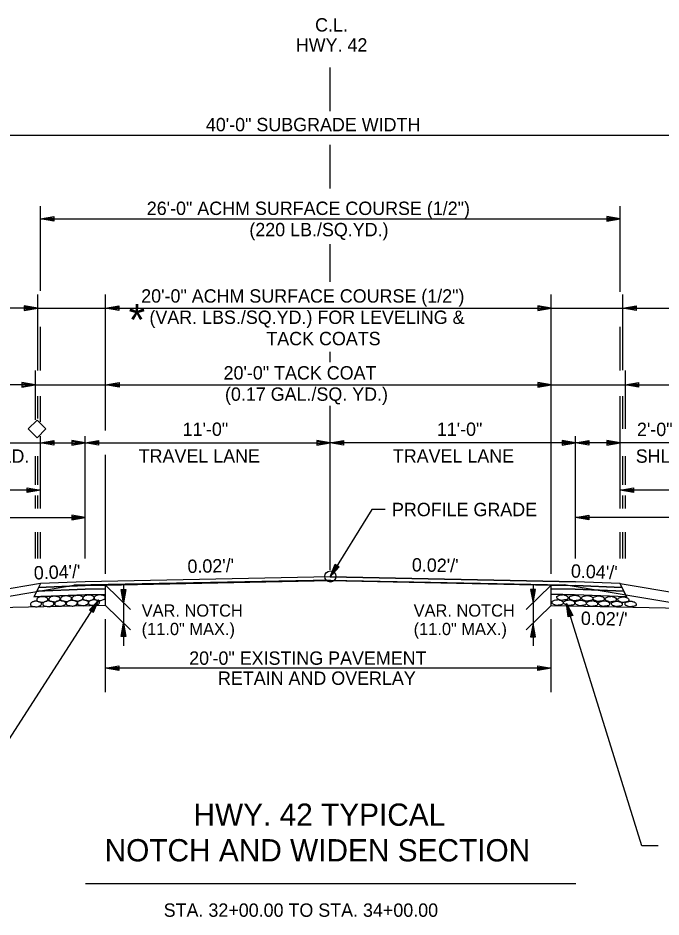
# Model space of a CAD drawing. Extents: x 1461570 to 1461697, y 1686711 to 1686957.
# Drawn here: x 1461592.73 to 1461621.58, y 1686771.55 to 1686811.92 of the extents above; entities that cross this region are included whole.
import ezdxf

# ---------------------------------------------------------------- set-up
doc = ezdxf.new("R2010")
doc.units = 0
for name, color, linetype in [('1', 7, 'Continuous'), ('10', 7, 'Continuous'), ('19', 7, 'Continuous'), ('20', 7, 'Continuous'), ('3', 7, 'Continuous'), ('42', 7, 'Continuous'), ('Default', 7, 'Continuous'), ('Level 1', 7, 'Continuous'), ('Level 9', 7, 'Continuous'), ('R_Draft', 7, 'Continuous'), ('R_Prop Surface', 7, 'Continuous')]:
    doc.layers.add(name, color=color, linetype=linetype)

# ---------------------------------------------------------------- blocks, each defined once
blk = doc.blocks.new('ROCKS')
at = {"layer": '1'}
blk.add_spline([(0.013, 0.06), (0.053, 0.053), (0.107, 0.033), (0.133, 0.013), (0.133, -0.007), (0.12, -0.033), (0.107, -0.04), (0.073, -0.053), (0.033, -0.067), (0.013, -0.067), (-0.02, -0.06), (-0.06, -0.053), (-0.087, -0.047), (-0.113, -0.02), (-0.113, -0.007), (-0.107, 0.02), (-0.087, 0.033), (-0.067, 0.047), (-0.033, 0.053), (-0.02, 0.06), (0.013, 0.06)], degree=3, dxfattribs=at)

msp = doc.modelspace()

# ---------------------------------------------------------------- linework, layer by layer
at = {"layer": '10'}
msp.add_lwpolyline([(1461593.585, 1686793.864), (1461593.983, 1686793.466), (1461593.585, 1686793.068), (1461593.187, 1686793.466)], close=True, dxfattribs=at)
at = {"layer": '19'}
for p, q in [((1461593.138, 1686790.605), (1461593.138, 1686790.815)), ((1461593.138, 1686790.815), (1461593.738, 1686790.71)), ((1461593.138, 1686790.76), (1461593.578, 1686790.725)), ((1461593.738, 1686790.71), (1461593.138, 1686790.605)), ((1461593.578, 1686790.695), (1461593.138, 1686790.655)), ((1461619.738, 1686790.71), (1461620.338, 1686790.815)), ((1461620.338, 1686790.605), (1461619.738, 1686790.71)), ((1461619.898, 1686790.725), (1461620.338, 1686790.76)), ((1461620.338, 1686790.655), (1461619.898, 1686790.695)), ((1461620.338, 1686790.815), (1461620.338, 1686790.605)), ((1461606.738, 1686786.821), (1461606.961, 1686787.387)), ((1461607.139, 1686787.278), (1461606.738, 1686786.821)), ((1461606.812, 1686786.962), (1461607.004, 1686787.355)), ((1461607.098, 1686787.299), (1461606.834, 1686786.95)), ((1461606.961, 1686787.387), (1461607.139, 1686787.278)), ((1461593.738, 1686786.521), (1461581.738, 1686784.521)), ((1461593.738, 1686786.521), (1461593.654, 1686786.351)), ((1461593.738, 1686786.521), (1461593.654, 1686786.351)), ((1461606.738, 1686786.821), (1461595.738, 1686786.601)), ((1461606.741, 1686786.654), (1461595.743, 1686786.434)), ((1461596.654, 1686785.535), (1461596.654, 1686786.452)), ((1461596.654, 1686786.452), (1461596.654, 1686786.452)), ((1461596.654, 1686786.286), (1461596.654, 1686786.452)), ((1461596.654, 1686786.452), (1461596.654, 1686786.452)), ((1461606.734, 1686786.654), (1461617.733, 1686786.434)), ((1461606.738, 1686786.821), (1461617.738, 1686786.601)), ((1461617.738, 1686786.601), (1461606.738, 1686786.821)), ((1461606.738, 1686786.654), (1461616.654, 1686786.456)), ((1461616.654, 1686785.539), (1461616.654, 1686786.456)), ((1461616.654, 1686786.289), (1461616.654, 1686786.456)), ((1461616.654, 1686786.456), (1461617.733, 1686786.434)), ((1461619.822, 1686786.351), (1461617.733, 1686786.434)), ((1461617.733, 1686786.434), (1461619.822, 1686786.35)), ((1461617.733, 1686786.434), (1461617.733, 1686786.434)), ((1461619.738, 1686786.521), (1461617.738, 1686786.601)), ((1461619.738, 1686786.521), (1461617.738, 1686786.601)), ((1461619.738, 1686786.521), (1461631.738, 1686784.521)), ((1461619.822, 1686786.351), (1461619.738, 1686786.521)), ((1461620.033, 1686785.925), (1461619.738, 1686786.521)), ((1461593.569, 1686786.18), (1461593.443, 1686785.925)), ((1461593.569, 1686786.18), (1461593.443, 1686785.925)), ((1461593.654, 1686786.351), (1461593.569, 1686786.18)), ((1461593.654, 1686786.351), (1461593.569, 1686786.18)), ((1461596.654, 1686786.286), (1461595.748, 1686786.268)), ((1461596.654, 1686786.036), (1461595.749, 1686786.017)), ((1461596.654, 1686786.286), (1461596.654, 1686786.286)), ((1461596.654, 1686786.036), (1461596.654, 1686786.286)), ((1461596.654, 1686786.286), (1461596.654, 1686786.286)), ((1461596.654, 1686786.036), (1461596.654, 1686786.036)), ((1461597.36, 1686786.259), (1461597.57, 1686786.259)), ((1461597.465, 1686785.659), (1461597.36, 1686786.259)), ((1461597.45, 1686785.819), (1461597.41, 1686786.259)), ((1461597.57, 1686786.259), (1461597.465, 1686785.659)), ((1461597.515, 1686786.259), (1461597.48, 1686785.819)), ((1461615.938, 1686786.252), (1461615.728, 1686786.252)), ((1461615.728, 1686786.252), (1461615.833, 1686785.652)), ((1461615.783, 1686786.252), (1461615.818, 1686785.812)), ((1461615.833, 1686785.652), (1461615.938, 1686786.252)), ((1461615.848, 1686785.812), (1461615.888, 1686786.252)), ((1461616.654, 1686786.289), (1461617.728, 1686786.268)), ((1461616.654, 1686786.039), (1461616.654, 1686786.289)), ((1461616.654, 1686786.039), (1461617.72, 1686786.018)), ((1461620.033, 1686785.925), (1461617.72, 1686786.018)), ((1461619.906, 1686786.18), (1461617.728, 1686786.268)), ((1461619.822, 1686786.35), (1461619.906, 1686786.18)), ((1461619.906, 1686786.18), (1461620.033, 1686785.925)), ((1461591.75, 1686778.631), (1461596.349, 1686785.793)), ((1461596.349, 1686785.793), (1461595.94, 1686785.341)), ((1461596.254, 1686785.665), (1461595.987, 1686785.316)), ((1461596.076, 1686785.258), (1461596.278, 1686785.65)), ((1461596.118, 1686785.231), (1461596.349, 1686785.793)), ((1461620.718, 1686774.738), (1461617.333, 1686785.632)), ((1461617.414, 1686785.03), (1461617.333, 1686785.632)), ((1461617.333, 1686785.632), (1461617.613, 1686785.091)), ((1461596.654, 1686785.535), (1461586.622, 1686785.335)), ((1461595.94, 1686785.341), (1461596.118, 1686785.231)), ((1461616.654, 1686785.539), (1461626.853, 1686785.335)), ((1461617.461, 1686785.045), (1461617.366, 1686785.475)), ((1461617.393, 1686785.484), (1461617.562, 1686785.078)), ((1461617.613, 1686785.091), (1461617.414, 1686785.03)), ((1461597.36, 1686784.142), (1461597.465, 1686784.742)), ((1461597.415, 1686784.142), (1461597.45, 1686784.582)), ((1461597.465, 1686784.742), (1461597.57, 1686784.142)), ((1461597.48, 1686784.582), (1461597.52, 1686784.142)), ((1461615.833, 1686784.735), (1461615.728, 1686784.135)), ((1461615.818, 1686784.575), (1461615.778, 1686784.135)), ((1461615.938, 1686784.135), (1461615.833, 1686784.735)), ((1461615.883, 1686784.135), (1461615.848, 1686784.575)), ((1461597.57, 1686784.142), (1461597.36, 1686784.142)), ((1461615.728, 1686784.135), (1461615.938, 1686784.135)), ((1461621.455, 1686774.738), (1461620.718, 1686774.738))]:
    msp.add_line(p, q, dxfattribs=at)
for points in [[(1461609.206, 1686789.847), (1461608.606, 1686789.846), (1461606.738, 1686786.821)], [(1461593.654, 1686786.351), (1461595.743, 1686786.434), (1461596.654, 1686786.452)], [(1461595.743, 1686786.434), (1461593.654, 1686786.351)], [(1461595.738, 1686786.601), (1461593.738, 1686786.521)], [(1461606.738, 1686786.821), (1461595.738, 1686786.601)], [(1461596.654, 1686786.452), (1461595.743, 1686786.434)], [(1461596.654, 1686786.452), (1461606.738, 1686786.654)], [(1461596.654, 1686786.452), (1461596.654, 1686786.452)], [(1461596.654, 1686786.452), (1461596.654, 1686786.452)], [(1461616.654, 1686786.456), (1461617.733, 1686786.434), (1461619.822, 1686786.351)], [(1461619.738, 1686786.521), (1461619.738, 1686786.521)], [(1461593.443, 1686785.925), (1461595.755, 1686786.018), (1461596.654, 1686786.036)], [(1461593.569, 1686786.18), (1461595.748, 1686786.268), (1461596.654, 1686786.286)], [(1461596.654, 1686786.286), (1461595.748, 1686786.263), (1461593.569, 1686786.18)], [(1461596.654, 1686786.286), (1461596.654, 1686786.286)], [(1461596.654, 1686786.286), (1461596.654, 1686786.286)], [(1461596.654, 1686786.286), (1461596.654, 1686786.286), (1461596.654, 1686786.286)], [(1461619.906, 1686786.18), (1461617.728, 1686786.268), (1461616.654, 1686786.289)], [(1461616.654, 1686786.289), (1461617.728, 1686786.268), (1461619.906, 1686786.18)], [(1461620.033, 1686785.925), (1461617.69, 1686786.017), (1461616.654, 1686786.039)]]:
    msp.add_lwpolyline(points, dxfattribs=at)
at = {"layer": '20'}
for p, q in [((1461586.622, 1686806.655), (1461626.853, 1686806.655)), ((1461593.738, 1686799.672), (1461593.738, 1686803.46)), ((1461619.738, 1686799.613), (1461619.738, 1686803.46)), ((1461593.738, 1686802.893), (1461594.338, 1686802.998)), ((1461594.338, 1686802.998), (1461594.338, 1686802.788)), ((1461619.138, 1686802.998), (1461619.138, 1686802.788)), ((1461619.738, 1686802.893), (1461619.138, 1686802.998)), ((1461593.738, 1686802.893), (1461619.738, 1686802.893)), ((1461594.338, 1686802.788), (1461593.738, 1686802.893)), ((1461593.898, 1686802.908), (1461594.338, 1686802.943)), ((1461594.338, 1686802.838), (1461593.898, 1686802.878)), ((1461619.578, 1686802.908), (1461619.138, 1686802.943)), ((1461619.138, 1686802.788), (1461619.738, 1686802.893)), ((1461619.138, 1686802.838), (1461619.578, 1686802.878)), ((1461593.611, 1686796.091), (1461593.611, 1686799.507)), ((1461596.654, 1686793.387), (1461596.654, 1686799.507)), ((1461616.654, 1686786.959), (1461616.654, 1686799.507)), ((1461619.864, 1686796.099), (1461619.864, 1686799.507)), ((1461593.011, 1686798.997), (1461593.011, 1686798.787)), ((1461593.611, 1686798.892), (1461593.011, 1686798.997)), ((1461593.451, 1686798.907), (1461593.011, 1686798.942)), ((1461596.654, 1686798.892), (1461597.254, 1686798.997)), ((1461596.814, 1686798.907), (1461597.254, 1686798.942)), ((1461597.254, 1686798.997), (1461597.254, 1686798.787)), ((1461616.054, 1686798.997), (1461616.054, 1686798.787)), ((1461616.654, 1686798.892), (1461616.054, 1686798.997)), ((1461616.494, 1686798.907), (1461616.054, 1686798.942)), ((1461619.864, 1686798.892), (1461620.464, 1686798.997)), ((1461620.024, 1686798.907), (1461620.464, 1686798.942)), ((1461620.464, 1686798.997), (1461620.464, 1686798.787)), ((1461593.611, 1686798.892), (1461573.526, 1686798.892)), ((1461593.011, 1686798.787), (1461593.611, 1686798.892)), ((1461593.011, 1686798.837), (1461593.451, 1686798.877)), ((1461593.611, 1686798.892), (1461596.654, 1686798.892)), ((1461596.654, 1686798.892), (1461616.654, 1686798.892)), ((1461597.254, 1686798.787), (1461596.654, 1686798.892)), ((1461597.254, 1686798.837), (1461596.814, 1686798.877)), ((1461616.054, 1686798.787), (1461616.654, 1686798.892)), ((1461616.054, 1686798.837), (1461616.494, 1686798.877)), ((1461616.654, 1686798.892), (1461619.864, 1686798.892)), ((1461619.864, 1686798.892), (1461640.297, 1686798.892)), ((1461620.464, 1686798.787), (1461619.864, 1686798.892)), ((1461620.464, 1686798.837), (1461620.024, 1686798.877)), ((1461593.738, 1686796.091), (1461593.738, 1686798.051)), ((1461619.738, 1686796.091), (1461619.738, 1686798.051)), ((1461593.506, 1686796.091), (1461593.506, 1686793.875)), ((1461619.969, 1686796.091), (1461619.969, 1686793.473)), ((1461593.501, 1686795.446), (1461573.523, 1686795.446)), ((1461592.901, 1686795.551), (1461592.901, 1686795.341)), ((1461593.501, 1686795.446), (1461592.901, 1686795.551)), ((1461593.341, 1686795.461), (1461592.901, 1686795.496)), ((1461592.901, 1686795.341), (1461593.501, 1686795.446)), ((1461592.901, 1686795.391), (1461593.341, 1686795.431)), ((1461593.501, 1686795.446), (1461596.66, 1686795.446)), ((1461596.66, 1686795.446), (1461597.26, 1686795.551)), ((1461597.26, 1686795.341), (1461596.66, 1686795.446)), ((1461596.66, 1686795.446), (1461616.654, 1686795.446)), ((1461596.82, 1686795.461), (1461597.26, 1686795.496)), ((1461597.26, 1686795.391), (1461596.82, 1686795.431)), ((1461597.26, 1686795.551), (1461597.26, 1686795.341)), ((1461616.054, 1686795.551), (1461616.054, 1686795.341)), ((1461616.654, 1686795.446), (1461616.054, 1686795.551)), ((1461616.494, 1686795.461), (1461616.054, 1686795.496)), ((1461616.054, 1686795.341), (1461616.654, 1686795.446)), ((1461616.054, 1686795.391), (1461616.494, 1686795.431)), ((1461616.654, 1686795.446), (1461619.969, 1686795.446)), ((1461619.969, 1686795.446), (1461620.569, 1686795.551)), ((1461619.969, 1686795.446), (1461640.297, 1686795.446)), ((1461620.569, 1686795.341), (1461619.969, 1686795.446)), ((1461620.129, 1686795.461), (1461620.569, 1686795.496)), ((1461620.569, 1686795.391), (1461620.129, 1686795.431)), ((1461620.569, 1686795.551), (1461620.569, 1686795.341)), ((1461593.611, 1686793.94), (1461593.611, 1686794.935)), ((1461593.738, 1686793.781), (1461593.738, 1686794.935)), ((1461619.738, 1686789.893), (1461619.738, 1686794.935)), ((1461619.864, 1686793.473), (1461619.864, 1686794.942)), ((1461593.738, 1686789.893), (1461593.738, 1686793.139)), ((1461593.738, 1686792.846), (1461594.338, 1686792.951)), ((1461593.898, 1686792.861), (1461594.338, 1686792.896)), ((1461594.338, 1686792.951), (1461594.338, 1686792.741)), ((1461595.138, 1686792.951), (1461595.138, 1686792.741)), ((1461595.738, 1686792.846), (1461595.138, 1686792.951)), ((1461595.578, 1686792.861), (1461595.138, 1686792.896)), ((1461595.738, 1686787.645), (1461595.738, 1686793.144)), ((1461595.738, 1686792.846), (1461596.338, 1686792.951)), ((1461595.898, 1686792.861), (1461596.338, 1686792.896)), ((1461596.338, 1686792.951), (1461596.338, 1686792.741)), ((1461606.138, 1686792.952), (1461606.138, 1686792.742)), ((1461606.738, 1686792.847), (1461606.138, 1686792.952)), ((1461606.578, 1686792.862), (1461606.138, 1686792.897)), ((1461606.738, 1686792.847), (1461607.338, 1686792.952)), ((1461606.898, 1686792.862), (1461607.338, 1686792.897)), ((1461607.338, 1686792.952), (1461607.338, 1686792.742)), ((1461617.138, 1686792.95), (1461617.138, 1686792.74)), ((1461617.738, 1686792.845), (1461617.138, 1686792.95)), ((1461617.578, 1686792.86), (1461617.138, 1686792.895)), ((1461617.738, 1686787.645), (1461617.738, 1686793.144)), ((1461617.738, 1686792.845), (1461618.338, 1686792.95)), ((1461617.898, 1686792.86), (1461618.338, 1686792.895)), ((1461618.338, 1686792.95), (1461618.338, 1686792.74)), ((1461619.143, 1686792.951), (1461619.143, 1686792.741)), ((1461619.743, 1686792.846), (1461619.143, 1686792.951)), ((1461619.583, 1686792.861), (1461619.143, 1686792.896)), ((1461594.338, 1686792.741), (1461593.738, 1686792.846)), ((1461594.338, 1686792.791), (1461593.898, 1686792.831)), ((1461595.138, 1686792.741), (1461595.738, 1686792.846)), ((1461595.138, 1686792.791), (1461595.578, 1686792.831)), ((1461596.338, 1686792.741), (1461595.738, 1686792.846)), ((1461596.338, 1686792.791), (1461595.898, 1686792.831)), ((1461606.138, 1686792.742), (1461606.738, 1686792.847)), ((1461606.138, 1686792.792), (1461606.578, 1686792.832)), ((1461607.338, 1686792.742), (1461606.738, 1686792.847)), ((1461607.338, 1686792.792), (1461606.898, 1686792.832)), ((1461617.138, 1686792.74), (1461617.738, 1686792.845)), ((1461617.138, 1686792.79), (1461617.578, 1686792.83)), ((1461618.338, 1686792.74), (1461617.738, 1686792.845)), ((1461618.338, 1686792.79), (1461617.898, 1686792.83)), ((1461619.143, 1686792.741), (1461619.743, 1686792.846)), ((1461619.143, 1686792.791), (1461619.583, 1686792.831)), ((1461593.506, 1686792.246), (1461593.506, 1686790.952)), ((1461593.611, 1686790.952), (1461593.611, 1686792.246)), ((1461596.654, 1686786.959), (1461596.654, 1686792.308)), ((1461619.864, 1686790.952), (1461619.864, 1686792.245)), ((1461619.969, 1686792.245), (1461619.969, 1686790.952)), ((1461593.506, 1686790.481), (1461593.506, 1686789.893)), ((1461593.611, 1686789.893), (1461593.611, 1686790.481)), ((1461619.864, 1686789.893), (1461619.864, 1686790.481)), ((1461619.969, 1686790.481), (1461619.969, 1686789.893)), ((1461595.138, 1686789.59), (1461595.138, 1686789.38)), ((1461595.738, 1686789.485), (1461595.138, 1686789.59)), ((1461595.578, 1686789.5), (1461595.138, 1686789.535)), ((1461595.138, 1686789.38), (1461595.738, 1686789.485)), ((1461595.138, 1686789.43), (1461595.578, 1686789.47)), ((1461617.738, 1686789.484), (1461618.338, 1686789.589)), ((1461618.338, 1686789.379), (1461617.738, 1686789.484)), ((1461617.898, 1686789.499), (1461618.338, 1686789.534)), ((1461618.338, 1686789.429), (1461617.898, 1686789.469)), ((1461618.338, 1686789.589), (1461618.338, 1686789.379)), ((1461593.506, 1686788.836), (1461593.506, 1686787.645)), ((1461593.611, 1686787.645), (1461593.611, 1686788.836)), ((1461593.738, 1686787.645), (1461593.738, 1686788.836)), ((1461619.738, 1686787.645), (1461619.738, 1686788.836)), ((1461619.864, 1686787.645), (1461619.864, 1686788.836)), ((1461619.969, 1686788.836), (1461619.969, 1686787.645)), ((1461596.654, 1686786.452), (1461597.776, 1686785.355)), ((1461616.654, 1686786.456), (1461615.533, 1686785.358)), ((1461596.654, 1686785.535), (1461597.776, 1686784.438)), ((1461616.654, 1686785.539), (1461615.533, 1686784.441)), ((1461596.654, 1686781.65), (1461596.654, 1686784.929)), ((1461616.654, 1686781.65), (1461616.654, 1686784.929)), ((1461596.654, 1686782.725), (1461597.254, 1686782.83)), ((1461597.254, 1686782.83), (1461597.254, 1686782.62)), ((1461616.054, 1686782.62), (1461616.054, 1686782.83)), ((1461616.054, 1686782.83), (1461616.654, 1686782.725)), ((1461616.654, 1686782.725), (1461596.654, 1686782.725)), ((1461597.254, 1686782.62), (1461596.654, 1686782.725)), ((1461596.814, 1686782.74), (1461597.254, 1686782.775)), ((1461597.254, 1686782.67), (1461596.814, 1686782.71)), ((1461616.054, 1686782.775), (1461616.494, 1686782.74)), ((1461616.654, 1686782.725), (1461616.054, 1686782.62)), ((1461616.494, 1686782.71), (1461616.054, 1686782.67))]:
    msp.add_line(p, q, dxfattribs=at)
for points in [[(1461597.465, 1686786.454), (1461597.465, 1686783.732)], [(1461615.833, 1686786.448), (1461615.833, 1686783.726)]]:
    msp.add_lwpolyline(points, dxfattribs=at)
at = {"layer": '3'}
msp.add_line((1461595.752, 1686773.057), (1461617.752, 1686773.057), dxfattribs=at)
at = {"layer": '42'}
for p, q in [((1461606.738, 1686807.731), (1461606.738, 1686809.686)), ((1461606.738, 1686804.262), (1461606.738, 1686806.217)), ((1461606.738, 1686800.065), (1461606.738, 1686801.765)), ((1461606.738, 1686796.462), (1461606.738, 1686796.932)), ((1461606.738, 1686787.142), (1461606.738, 1686794.496)), ((1461590.233, 1686792.846), (1461594.743, 1686792.846)), ((1461594.738, 1686792.846), (1461606.738, 1686792.847)), ((1461617.738, 1686792.845), (1461606.738, 1686792.846)), ((1461622.946, 1686792.846), (1461617.732, 1686792.845)), ((1461581.738, 1686789.485), (1461595.738, 1686789.485)), ((1461631.738, 1686789.484), (1461617.738, 1686789.484))]:
    msp.add_line(p, q, dxfattribs=at)
msp.add_circle((1461606.743, 1686786.839), 0.25, dxfattribs=at)
at = {"layer": 'Level 9'}
for p, q in [((1461593.738, 1686790.71), (1461586.622, 1686790.71)), ((1461626.853, 1686790.71), (1461619.738, 1686790.71))]:
    msp.add_line(p, q, dxfattribs=at)
at = {"layer": 'R_Draft'}
for p, q in [((1461583.437, 1686784.478), (1461595.238, 1686786.445)), ((1461606.738, 1686786.675), (1461595.238, 1686786.445)), ((1461606.738, 1686786.675), (1461617.238, 1686786.465)), ((1461629.039, 1686784.498), (1461617.238, 1686786.465))]:
    msp.add_line(p, q, dxfattribs=at)
at = {"layer": 'R_Prop Surface'}
for p, q in [((1461595.743, 1686786.434), (1461593.654, 1686786.351)), ((1461595.738, 1686786.601), (1461593.738, 1686786.521)), ((1461595.761, 1686786.018), (1461593.443, 1686785.925)), ((1461595.748, 1686786.268), (1461593.569, 1686786.18))]:
    msp.add_line(p, q, dxfattribs=at)

# ---------------------------------------------------------------- block references
at = {"layer": 'Level 1'}
for p, xscale, yscale, rotation in [((1461595.871, 1686785.884), 2.011654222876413, 2.011654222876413, 1.8263814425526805), ((1461596.376, 1686785.893), 2.011654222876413, 2.011654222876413, 1.8263814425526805), ((1461617.175, 1686785.899), 2.011654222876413, -2.011654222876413, 178.17361855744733), ((1461593.515, 1686785.609), 2.011654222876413, 2.011654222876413, 1.8263814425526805), ((1461593.801, 1686785.815), 2.011654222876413, 2.011654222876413, 1.8263814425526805), ((1461594.073, 1686785.618), 2.011654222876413, 2.011654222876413, 1.8263814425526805), ((1461594.345, 1686785.837), 2.011654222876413, 2.011654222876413, 1.8263814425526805), ((1461594.605, 1686785.634), 2.011654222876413, 2.011654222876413, 1.8263814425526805), ((1461594.862, 1686785.851), 2.011654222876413, 2.011654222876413, 1.8263814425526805), ((1461595.122, 1686785.645), 2.011654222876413, 2.011654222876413, 1.8263814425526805), ((1461595.375, 1686785.869), 2.011654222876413, 2.011654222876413, 1.8263814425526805), ((1461595.625, 1686785.663), 2.011654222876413, 2.011654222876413, 1.8263814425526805), ((1461596.115, 1686785.668), 2.011654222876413, 2.011654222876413, 1.8263814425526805), ((1461616.957, 1686785.674), 2.011654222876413, -2.011654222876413, 178.17361855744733), ((1461617.473, 1686785.665), 2.011654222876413, -2.011654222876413, 178.17361855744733), ((1461617.733, 1686785.878), 2.011654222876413, -2.011654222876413, 178.17361855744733), ((1461617.994, 1686785.655), 2.011654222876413, -2.011654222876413, 178.17361855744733), ((1461618.288, 1686785.864), 2.011654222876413, -2.011654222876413, 178.17361855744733), ((1461618.507, 1686785.629), 2.011654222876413, -2.011654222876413, 178.17361855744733), ((1461618.802, 1686785.848), 2.011654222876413, -2.011654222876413, 178.17361855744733), ((1461619.043, 1686785.628), 2.011654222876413, -2.011654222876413, 178.17361855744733), ((1461619.344, 1686785.826), 2.011654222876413, -2.011654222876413, 178.17361855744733), ((1461619.616, 1686785.614), 1.9502040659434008, -1.9502040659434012, 178.17361855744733), ((1461619.907, 1686785.805), 2.011654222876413, -2.011654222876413, 178.17361855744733), ((1461620.231, 1686785.608), 2.011654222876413, -2.011654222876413, 178.17361855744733)]:
    msp.add_blockref('ROCKS', p, dxfattribs=dict(at, xscale=xscale, yscale=yscale, rotation=rotation))

# ---------------------------------------------------------------- texts
at = {"layer": '10'}
msp.add_text('*', height=1.422, rotation=359.9954, dxfattribs=at).set_placement((1461597.693, 1686797.654))
for s, p in [('VAR. NOTCH', (1461598.277, 1686785.037)), ('VAR. NOTCH', (1461610.479, 1686785.037)), ('(11.0" MAX.)', (1461598.277, 1686784.208)), ('(11.0" MAX.)', (1461610.479, 1686784.208))]:
    msp.add_text(s, height=0.55, dxfattribs=at).set_placement(p)
at = {"layer": '19'}
for s, height, rotation, p in [('11\'-0"', 0.6, 360, (1461600.115, 1686793.152)), ('SHLD.', 0.6, 360, (1461590.875, 1686791.946)), ('TRAVEL LANE', 0.6, 360, (1461598.143, 1686791.952)), ('PROFILE GRADE', 0.6, 360, (1461609.506, 1686789.547)), ("0.02'/'", 0.6, 1.1458, (1461600.337, 1686786.993)), ("0.02'/'", 0.6, 358.8542, (1461610.394, 1686787.068)), ("0.04'/'", 0.6, 2.1602, (1461593.449, 1686786.699)), ("0.04'/'", 0.6, 357.8398, (1461617.525, 1686786.793)), ("0.02'/'", 0.6, 358.8542, (1461617.975, 1686784.666)), ('HWY. 42 TYPICAL ', 1, 359.9954, (1461600.602, 1686775.646)), ('NOTCH AND WIDEN SECTION', 1, 359.9954, (1461596.614, 1686774.047)), ('STA. 32+00.00 TO STA. 34+00.00', 0.6, 359.9954, (1461599.265, 1686771.559))]:
    msp.add_text(s, height=height, rotation=rotation, dxfattribs=at).set_placement(p)
for s, p in [('11\'-0"', (1461611.518, 1686793.152)), ('2\'-0"', (1461620.497, 1686793.145)), ('TRAVEL LANE', (1461609.545, 1686791.952)), ('SHLD.', (1461620.443, 1686791.945))]:
    msp.add_text(s, height=0.6, dxfattribs=at).set_placement(p)
at = {"layer": 'Default'}
for s, height, p in [('40\'-0" SUBGRADE WIDTH', 0.60001, (1461601.157, 1686806.829)), ('26\'-0" ACHM SURFACE COURSE (1/2")', 0.60001, (1461598.506, 1686803.071)), ('(220 LB./SQ.YD.)', 0.60001, (1461603.108, 1686802.115)), ('20\'-0" ACHM SURFACE COURSE (1/2")', 0.60001, (1461598.257, 1686799.135)), ('(VAR. LBS./SQ.YD.) FOR LEVELING &', 0.60001, (1461598.625, 1686798.179)), ('TACK COATS', 0.6, (1461603.87, 1686797.223)), ('20\'-0" TACK COAT', 0.60001, (1461601.951, 1686795.683)), ('(0.17 GAL./SQ. YD.)', 0.60001, (1461602.014, 1686794.727))]:
    msp.add_text(s, height=height, dxfattribs=at).set_placement(p)
at = {"layer": 'R_Draft'}
for s, p in [('C.L.', (1461606.057, 1686811.307)), ('HWY. 42', (1461605.192, 1686810.407))]:
    msp.add_text(s, height=0.6, rotation=360, dxfattribs=at).set_placement(p)
for s, p in [('20\'-0" EXISTING PAVEMENT', (1461600.408, 1686782.874)), ('RETAIN AND OVERLAY', (1461601.7, 1686781.974))]:
    msp.add_text(s, height=0.6, dxfattribs=at).set_placement(p)

doc.saveas('drawing.dxf')
